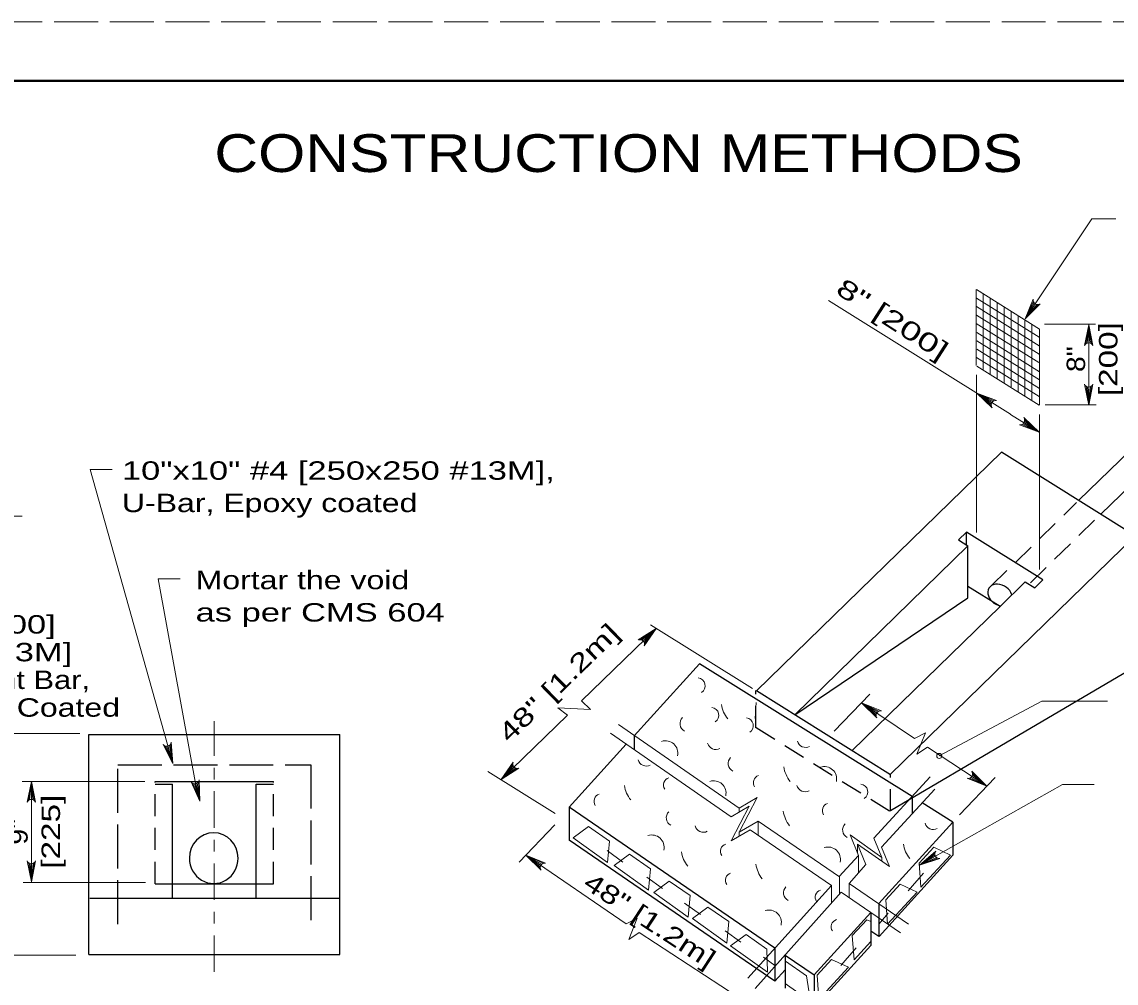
# Model space of a CAD drawing. Extents: x 1083.1 to 1117.1, y 697.4 to 741.4.
# Drawn here: x 1092.41 to 1101.68, y 733.21 to 741.35 of the extents above; entities that cross this region are included whole.
import ezdxf
from ezdxf.enums import TextEntityAlignment as Align

# ---------------------------------------------------------------- set-up
doc = ezdxf.new("R2010")
doc.units = 0
doc.header["$LTSCALE"] = 0.062
for name, pattern in [('DOT_DASHED', [7.7, 5, -1.2, 0.3, -1.2]), ('LONG_DASHED', [7.5, 6, -1.5]), ('MEDIUM_DASHED', [4.5, 3, -1.5])]:
    doc.linetypes.add(name, pattern=pattern)
doc.layers.add('1', color=7, linetype='Continuous', lineweight=13)

msp = doc.modelspace()

# ---------------------------------------------------------------- linework, layer by layer
at = {"layer": '1', "lineweight": 25}
for p, q in [((1085.12642, 740.85408), (1116.62642, 740.85408)), ((1101.35767, 737.30017), (1102.00192, 737.92825)), ((1101.54458, 737.18333), (1102.16675, 737.78975)), ((1098.62958, 735.68725), (1100.70367, 737.70908)), ((1101.83592, 737.00125), (1100.70367, 737.70908)), ((1099.764, 734.98167), (1101.83592, 737.00125)), ((1100.34017, 736.96608), (1100.40908, 737.03325)), ((1101.05608, 736.62858), (1100.40908, 737.03325)), ((1100.40908, 736.923), (1100.40908, 737.03325)), ((1098.95342, 735.48483), (1100.421, 736.91542)), ((1100.34017, 736.96608), (1100.421, 736.91542)), ((1100.421, 736.47508), (1100.421, 736.91542)), ((1100.69392, 736.4015), (1100.421, 736.57217)), ((1100.69208, 736.40342), (1100.90617, 736.61208)), ((1098.95342, 735.48483), (1100.421, 736.47508)), ((1099.4385, 735.1815), (1100.69233, 736.40367)), ((1097.593, 735.30817), (1098.148, 735.91767)), ((1099.94717, 734.79267), (1098.148, 735.91767)), ((1099.764, 734.67442), (1101.83592, 735.895)), ((1099.764, 734.97792), (1098.62958, 735.68725)), ((1092.977, 733.45633), (1092.977, 735.3185)), ((1092.977, 735.3185), (1095.101, 735.3185)), ((1095.101, 733.45633), (1095.101, 735.3185)), ((1097.04267, 734.70375), (1097.52775, 735.2365)), ((1097.593, 735.30817), (1097.593, 735.19125)), ((1093.53758, 734.92175), (1094.54058, 734.92175)), ((1093.53758, 734.897), (1093.685, 734.897)), ((1093.685, 733.92975), (1093.685, 734.897)), ((1094.393, 733.93225), (1094.393, 734.897)), ((1094.393, 734.897), (1094.54058, 734.897)), ((1099.94717, 734.79267), (1099.94717, 734.64633)), ((1097.04267, 734.70375), (1097.04267, 734.42308)), ((1098.78633, 733.51), (1097.04267, 734.70375)), ((1100.29392, 734.57583), (1100.03242, 734.73933)), ((1099.66692, 733.88725), (1100.29392, 734.57583)), ((1100.29392, 734.57583), (1100.29392, 734.29517)), ((1098.78633, 733.22933), (1097.04267, 734.42308)), ((1099.668, 733.60775), (1100.29392, 734.29517)), ((1093.683, 734.055), (1094.39467, 734.055)), ((1092.9855, 733.93208), (1095.09617, 733.93208)), ((1099.66692, 733.88725), (1099.66692, 733.60658)), ((1099.11717, 733.2835), (1099.59808, 733.81167)), ((1099.59808, 733.81167), (1099.59808, 733.531)), ((1099.66692, 733.60658), (1099.59808, 733.65375)), ((1098.78633, 733.51), (1098.78633, 733.22933)), ((1099.11717, 733.00283), (1099.59808, 733.531)), ((1092.977, 733.45633), (1095.101, 733.45633)), ((1098.87317, 733.45058), (1099.11717, 733.2835)), ((1098.87317, 733.45058), (1098.87317, 733.16992)), ((1098.78633, 733.22933), (1098.87317, 733.32467)), ((1099.11717, 733.2835), (1099.11717, 733.00283))]:
    msp.add_line(p, q, dxfattribs=at)
at = {"layer": '1'}
for p, q in [((1100.90592, 738.83825), (1101.46942, 739.68592)), ((1101.46942, 739.68592), (1101.67183, 739.68592)), ((1100.49067, 738.44467), (1100.49067, 739.08708)), ((1101.02683, 738.75192), (1100.49208, 739.08625)), ((1100.54967, 738.40483), (1100.54967, 739.05017)), ((1100.782, 738.03033), (1099.2385, 738.995)), ((1101.02233, 738.68317), (1100.49208, 739.01467)), ((1101.023, 738.61108), (1100.49267, 738.94258)), ((1100.60867, 738.36867), (1100.60867, 739.01333)), ((1100.66767, 738.335), (1100.66767, 738.97642)), ((1100.72667, 738.29892), (1100.72667, 738.93958)), ((1100.97533, 738.98442), (1100.90592, 738.83825)), ((1100.98167, 738.97375), (1100.90592, 738.83825)), ((1100.99017, 738.96617), (1100.90592, 738.83825)), ((1101.00375, 738.96058), (1100.90592, 738.83825)), ((1101.01583, 738.96), (1100.90592, 738.83825)), ((1101.02233, 738.539), (1100.49208, 738.8705)), ((1100.78567, 738.26275), (1100.78567, 738.90267)), ((1100.84467, 738.22283), (1100.84467, 738.86583)), ((1101.0205, 738.46833), (1100.49025, 738.79983)), ((1100.90367, 738.19042), (1100.90367, 738.82892)), ((1100.96267, 738.14783), (1100.96267, 738.79192)), ((1101.02583, 738.10783), (1101.02583, 738.7525)), ((1101.49942, 738.79292), (1101.06808, 738.79292)), ((1101.41892, 738.627), (1101.44375, 738.78908)), ((1101.42933, 738.63308), (1101.44375, 738.78908)), ((1101.44375, 738.63592), (1101.44375, 738.78908)), ((1101.45508, 738.63425), (1101.44375, 738.78908)), ((1101.46617, 738.62883), (1101.44375, 738.78908)), ((1101.02683, 738.32175), (1100.49642, 738.65308)), ((1101.02733, 738.39108), (1100.49708, 738.7225)), ((1101.02608, 738.24958), (1100.49592, 738.581)), ((1101.02425, 738.18008), (1100.494, 738.5115)), ((1101.02492, 738.10808), (1100.49458, 738.4395)), ((1100.49208, 737.02975), (1100.49208, 738.36342)), ((1100.62425, 738.12892), (1100.49442, 738.21008)), ((1100.619, 738.11525), (1100.49442, 738.21008)), ((1100.61875, 738.10317), (1100.49442, 738.21008)), ((1100.63167, 738.13767), (1100.49442, 738.21008)), ((1100.64217, 738.14417), (1100.49442, 738.21008)), ((1101.42133, 738.26808), (1101.44375, 738.10783)), ((1101.43242, 738.26267), (1101.44375, 738.10783)), ((1101.4685, 738.27), (1101.44375, 738.10783)), ((1101.45808, 738.26383), (1101.44375, 738.10783)), ((1101.44375, 738.261), (1101.44375, 738.10783)), ((1101.50517, 738.10983), (1101.07392, 738.10983)), ((1101.02467, 737.87867), (1100.78133, 738.02942)), ((1101.02725, 736.717), (1101.02725, 738.02783)), ((1100.87683, 737.94458), (1101.02467, 737.87867)), ((1100.88733, 737.95108), (1101.02467, 737.87867)), ((1100.89475, 737.95983), (1101.02467, 737.87867)), ((1100.9, 737.9735), (1101.02467, 737.87867)), ((1100.90025, 737.98558), (1101.02467, 737.87867)), ((1092.4125, 737.16733), (1090.73225, 737.16733)), ((1098.59508, 735.70875), (1097.73383, 736.24742)), ((1097.6475, 736.12167), (1097.781, 736.21692)), ((1097.65917, 736.1185), (1097.781, 736.21692)), ((1097.67117, 736.11017), (1097.781, 736.21692)), ((1097.67792, 736.10083), (1097.781, 736.21692)), ((1097.68175, 736.08908), (1097.781, 736.21692)), ((1099.59025, 735.66092), (1099.28742, 735.34542)), ((1099.64875, 735.50258), (1099.52058, 735.58642)), ((1099.64325, 735.489), (1099.52058, 735.58642)), ((1099.64275, 735.47692), (1099.52058, 735.58642)), ((1099.65633, 735.51117), (1099.52058, 735.58642)), ((1099.667, 735.51742), (1099.52058, 735.58642)), ((1099.96708, 735.28325), (1099.52058, 735.58642)), ((1093.65942, 735.22658), (1093.68692, 735.07233)), ((1093.66783, 735.23525), (1093.68692, 735.07233)), ((1093.62283, 735.22092), (1093.68692, 735.07233)), ((1093.63492, 735.21858), (1093.68692, 735.07233)), ((1093.64625, 735.22), (1093.68692, 735.07233)), ((1100.58125, 734.8805), (1100.07775, 735.21092)), ((1096.56625, 735.06375), (1096.467, 734.936)), ((1096.57008, 735.052), (1096.467, 734.936)), ((1096.57683, 735.04275), (1096.467, 734.936)), ((1096.92392, 734.65042), (1096.35617, 735.00542)), ((1096.58883, 735.03442), (1096.467, 734.936)), ((1096.6005, 735.03125), (1096.467, 734.936)), ((1100.65092, 734.955), (1100.34792, 734.6395)), ((1100.43483, 734.94942), (1100.58125, 734.8805)), ((1100.44542, 734.95567), (1100.58125, 734.8805)), ((1100.453, 734.96425), (1100.58125, 734.8805)), ((1100.45858, 734.97792), (1100.58125, 734.8805)), ((1100.45908, 734.98992), (1100.58125, 734.8805)), ((1093.45, 734.92175), (1092.41233, 734.92175)), ((1092.46508, 734.75958), (1092.48983, 734.92175)), ((1092.47542, 734.76575), (1092.48983, 734.92175)), ((1092.48983, 734.071), (1092.48983, 734.92175)), ((1092.48983, 734.76858), (1092.48983, 734.92175)), ((1092.50117, 734.76692), (1092.48983, 734.92175)), ((1092.51225, 734.7615), (1092.48983, 734.92175)), ((1093.85817, 734.90408), (1093.91617, 734.753)), ((1093.87017, 734.90125), (1093.91617, 734.753)), ((1093.8815, 734.90217), (1093.91617, 734.753)), ((1093.89492, 734.90825), (1093.91617, 734.753)), ((1093.90375, 734.91658), (1093.91617, 734.753)), ((1100.0115, 734.21167), (1101.22067, 734.89417)), ((1101.22067, 734.89417), (1101.49075, 734.89417)), ((1098.48333, 734.69517), (1098.48333, 734.66167)), ((1098.64558, 734.58517), (1098.64558, 734.46517)), ((1099.33208, 734.11417), (1098.64558, 734.58517)), ((1096.92383, 734.55408), (1096.621, 734.23858)), ((1098.48333, 734.49092), (1098.48333, 734.45708)), ((1099.26433, 734.04067), (1098.57758, 734.51183)), ((1099.42208, 734.46833), (1099.49342, 734.29483)), ((1099.4855, 734.39108), (1099.4855, 734.31283)), ((1097.36533, 734.33467), (1097.4995, 734.23767)), ((1100.13975, 734.31025), (1100.0115, 734.21167)), ((1100.1405, 734.29792), (1100.0115, 734.21167)), ((1092.46742, 734.23125), (1092.48983, 734.071)), ((1092.4785, 734.22583), (1092.48983, 734.071)), ((1092.51458, 734.23317), (1092.48983, 734.071)), ((1092.50425, 734.227), (1092.48983, 734.071)), ((1092.48983, 734.22417), (1092.48983, 734.071)), ((1096.80475, 734.21267), (1096.67658, 734.2965)), ((1096.79925, 734.19908), (1096.67658, 734.2965)), ((1096.79875, 734.187), (1096.67658, 734.2965)), ((1096.81233, 734.22125), (1096.67658, 734.2965)), ((1096.823, 734.2275), (1096.67658, 734.2965)), ((1097.52708, 733.71425), (1096.67658, 734.2965)), ((1099.33117, 734.11475), (1099.49342, 734.29483)), ((1099.49342, 734.29483), (1099.49342, 734.14642)), ((1099.69192, 734.27808), (1099.69192, 734.2455)), ((1100.14467, 734.28725), (1100.0115, 734.21167)), ((1100.15425, 734.27617), (1100.0115, 734.21167)), ((1100.16475, 734.27017), (1100.0115, 734.21167)), ((1099.33308, 734.11433), (1099.33308, 733.96658)), ((1099.91475, 733.99533), (1100.04525, 734.1445)), ((1093.45692, 734.06608), (1092.41942, 734.06608)), ((1097.70083, 734.111), (1097.835, 734.014)), ((1098.55658, 733.25492), (1099.26433, 734.04067)), ((1099.26417, 734.04042), (1099.26417, 733.89267)), ((1099.41433, 734.05775), (1099.41433, 733.93775)), ((1098.61942, 733.16592), (1099.34742, 733.98267)), ((1099.84967, 733.63908), (1099.34758, 733.98358)), ((1098.02133, 733.891), (1098.1555, 733.794)), ((1099.66692, 733.7135), (1099.74617, 733.80408)), ((1098.36425, 733.65608), (1098.49842, 733.55908)), ((1098.71317, 732.93875), (1097.63775, 733.64192)), ((1099.3445, 733.3615), (1099.475, 733.51067)), ((1092.86575, 733.45017), (1090.709, 733.45017)), ((1098.68858, 733.43242), (1098.78633, 733.36175))]:
    msp.add_line(p, q, dxfattribs=at)
at = {"layer": '1', "linetype": 'MEDIUM_DASHED', "lineweight": 25}
for p, q in [((1100.61717, 736.57675), (1101.34083, 737.28225)), ((1100.94992, 736.60367), (1101.54458, 737.18342)), ((1098.62475, 735.37525), (1098.62475, 735.69017)), ((1099.75583, 734.66867), (1098.62517, 735.37542)), ((1099.764, 734.66967), (1099.764, 734.98167)), ((1093.53758, 734.055), (1093.53758, 734.92175)), ((1094.54058, 734.055), (1094.54058, 734.92175)), ((1093.53758, 734.055), (1093.68542, 734.055)), ((1094.38983, 734.055), (1094.54058, 734.055))]:
    msp.add_line(p, q, dxfattribs=at)
at = {"layer": '1', "linetype": 'MEDIUM_DASHED'}
msp.add_line((1098.62017, 735.4545), (1098.62783, 735.58917), dxfattribs=at)
at = {"layer": '1', "linetype": 'DOT_DASHED'}
msp.add_line((1094.039, 733.30725), (1094.039, 735.431), dxfattribs=at)
at = {"layer": '1', "linetype": 'LONG_DASHED'}
msp.add_lwpolyline([(1083.12642, 719.35408), (1117.12642, 719.35408), (1117.12642, 741.35408), (1083.12642, 741.35408)], close=True, dxfattribs=at)
at = {"layer": '1', "lineweight": 40}
msp.add_lwpolyline([(1085.12642, 740.85408), (1116.62642, 740.85408), (1116.62642, 719.85408), (1085.12642, 719.85408)], close=True, dxfattribs=at)
msp.add_lwpolyline([(1085.12642, 740.85408), (1116.62642, 740.85408), (1116.62642, 719.85408), (1085.12642, 719.85408)], close=True, dxfattribs=at)
at = {"layer": '1'}
for points in [[(1101.03283, 738.96658), (1100.90592, 738.83825), (1100.97375, 739.0055)], [(1101.40833, 738.61208), (1101.44375, 738.78908), (1101.47908, 738.61208)], [(1101.44375, 738.10783), (1101.44375, 738.56575), (1101.44375, 738.78908)], [(1101.47908, 738.28483), (1101.44375, 738.10783), (1101.40833, 738.28483)], [(1100.62567, 738.08625), (1100.49442, 738.21008), (1100.66325, 738.14633)], [(1100.89333, 738.0025), (1101.02467, 737.87867), (1100.85575, 737.94242)], [(1093.17508, 737.56367), (1092.98908, 737.56367), (1093.68783, 735.072)], [(1093.75075, 736.6365), (1093.56475, 736.6365), (1093.89392, 734.82675)], [(1096.467, 734.936), (1097.02967, 735.48292), (1096.94833, 735.5455), (1097.22517, 735.53092), (1097.14958, 735.60292), (1097.781, 736.21692)], [(1097.62942, 736.11892), (1097.781, 736.21692), (1097.67875, 736.06817)], [(1100.17725, 735.13675), (1101.04675, 735.60017), (1101.60267, 735.60017)], [(1099.64933, 735.45992), (1099.52058, 735.58642), (1099.68808, 735.51917)], [(1087.54775, 735.32775), (1090.51608, 735.32775), (1092.9005, 735.32775)], [(1097.39433, 735.32883), (1098.41533, 734.62183), (1098.56717, 734.71083), (1098.41533, 734.41758), (1098.57758, 734.51183)], [(1097.46233, 735.40217), (1098.48333, 734.69517), (1098.63517, 734.78417), (1098.48333, 734.49092), (1098.64558, 734.58517)], [(1099.96708, 735.28325), (1100.06075, 735.33275), (1099.98883, 735.15158), (1100.07775, 735.21092)], [(1093.67408, 735.25242), (1093.68692, 735.07233), (1093.60583, 735.23358)], [(1096.61858, 735.034), (1096.467, 734.936), (1096.56925, 735.08475)], [(1100.10108, 734.96058), (1099.62442, 734.44067), (1099.69192, 734.27808), (1099.42208, 734.46833)], [(1100.4525, 735.007), (1100.58125, 734.8805), (1100.41375, 734.94767)], [(1092.45442, 734.74475), (1092.48983, 734.92175), (1092.52525, 734.74475)], [(1093.91067, 734.93342), (1093.91617, 734.753), (1093.84167, 734.91742)], [(1100.139, 734.85558), (1099.68775, 734.36333), (1099.75533, 734.20075), (1099.4855, 734.39108), (1099.55675, 734.2175)], [(1100.18292, 734.26825), (1100.0115, 734.21167), (1100.14792, 734.32983)], [(1092.52525, 734.248), (1092.48983, 734.071), (1092.45442, 734.248)], [(1096.80533, 734.17), (1096.67658, 734.2965), (1096.84408, 734.22925)], [(1099.91767, 733.71242), (1099.41433, 734.05775), (1099.55675, 734.2175)], [(1097.52708, 733.71425), (1097.62075, 733.76375), (1097.54883, 733.58258), (1097.63775, 733.64192)], [(1099.59808, 733.56442), (1099.45642, 733.41), (1099.4415, 733.61508), (1099.5645, 733.74933), (1099.59808, 733.73342)], [(1098.87317, 733.3975), (1098.87492, 733.39883), (1099.05217, 733.275), (1099.08667, 733.05583), (1098.87317, 733.2095)]]:
    msp.add_lwpolyline(points, dxfattribs=at)
at = {"layer": '1', "lineweight": 25}
msp.add_lwpolyline([(1100.90617, 736.61208), (1100.98717, 736.56142), (1101.05608, 736.62858)], dxfattribs=at)
at = {"layer": '1', "linetype": 'LONG_DASHED', "lineweight": 25}
msp.add_lwpolyline([(1093.2225, 733.712), (1093.2225, 735.06283), (1094.85558, 735.06283), (1094.85558, 733.712)], dxfattribs=at)
at = {"layer": '1'}
for points in [[(1097.07842, 734.44283), (1097.20883, 734.53975), (1097.38608, 734.41592), (1097.36908, 734.234)], [(1097.42508, 734.20792), (1097.5555, 734.30483), (1097.73275, 734.181), (1097.71575, 733.99908)], [(1100.02292, 734.02508), (1100.008, 734.23017), (1100.131, 734.36442), (1100.27258, 734.29725)], [(1097.7605, 733.9805), (1097.89092, 734.07742), (1098.06817, 733.95358), (1098.05117, 733.77167)], [(1099.73967, 733.712), (1099.72475, 733.91708), (1099.84775, 734.05133), (1099.98933, 733.98417)], [(1098.0885, 733.7605), (1098.21892, 733.85742), (1098.39617, 733.73358), (1098.37917, 733.55167)], [(1098.41125, 733.52783), (1098.54167, 733.62475), (1098.71892, 733.50092), (1098.72292, 733.30492)], [(1099.15817, 733.07442), (1099.14325, 733.2795), (1099.26625, 733.41375), (1099.40783, 733.34658)]]:
    msp.add_lwpolyline(points, close=True, dxfattribs=at)
msp.add_circle((1100.17725, 735.13675), 0.02142, dxfattribs=at)
for centre, radius, start, end in [((1101.01111, 738.99801), 0.0382, 168.72921, 304.55533), ((1101.44375, 738.59781), 0.0382, 22.08782, 157.91395), ((1101.44368, 738.29914), 0.0382, 202.08782, 337.91395), ((1100.65661, 738.10874), 0.0382, 80.07633, 215.90246), ((1100.8624, 737.98), 0.0382, 260.07633, 35.90246), ((1097.64389, 736.08352), 0.0382, 336.28517, 112.1113), ((1098.12842, 735.73125), 0.06689, 303.67027, 82.84336), ((1098.24442, 735.48075), 0.06689, 303.67027, 82.84336), ((1098.59683, 735.61533), 0.26761, 188.97541, 218.01059), ((1099.68071, 735.48175), 0.0382, 78.90799, 214.73412), ((1098.05425, 735.41125), 0.07212, 135, 242.45942), ((1098.5365, 735.39267), 0.06689, 303.67027, 82.84336), ((1093.63613, 735.25678), 0.0382, 217.46338, 353.28951), ((1097.8595, 735.16075), 0.10462, 347.15932, 108.38347), ((1098.28608, 735.26275), 0.072, 194.8887, 297.82099), ((1099.04667, 735.28125), 0.072, 194.8887, 297.82099), ((1096.60411, 735.06937), 0.0382, 156.27266, 292.09878), ((1097.69717, 735.12358), 0.072, 194.8887, 297.82099), ((1098.46233, 735.07267), 0.07212, 135, 242.45942), ((1099.1255, 735.0865), 0.26761, 188.97541, 218.01059), ((1099.20433, 734.94275), 0.10462, 347.15932, 108.38347), ((1097.90583, 734.89167), 0.06313, 107.11941, 214.34733), ((1098.66642, 734.91017), 0.06313, 107.11941, 214.34733), ((1100.42115, 734.98511), 0.0382, 258.90799, 34.73412), ((1093.87295, 734.93932), 0.0382, 215.13546, 350.96158), ((1097.776, 734.92883), 0.26761, 188.97541, 218.01059), ((1098.26758, 734.82217), 0.10462, 347.15932, 108.38347), ((1099.042, 734.90558), 0.072, 194.8887, 297.82099), ((1099.50575, 734.83133), 0.06689, 303.67027, 82.84336), ((1092.48988, 734.73042), 0.0382, 22.08782, 157.91395), ((1097.31692, 734.7525), 0.06313, 107.11941, 214.34733), ((1099.12083, 734.71083), 0.26761, 188.97541, 218.01059), ((1099.25067, 734.67367), 0.06313, 107.11941, 214.34733), ((1097.93833, 734.61342), 0.07212, 135, 242.45942), ((1098.17942, 734.56233), 0.072, 194.8887, 297.82099), ((1099.43158, 734.51133), 0.07212, 135, 242.45942), ((1100.12717, 734.5855), 0.072, 194.8887, 297.82099), ((1097.74358, 734.36292), 0.10462, 347.15932, 108.38347), ((1098.38808, 734.33042), 0.06313, 107.11941, 214.34733), ((1100.13792, 734.43267), 0.26761, 188.97541, 218.01059), ((1098.25825, 734.36758), 0.26761, 188.97541, 218.01059), ((1099.23683, 734.26083), 0.10462, 347.15932, 108.38347), ((1100.17782, 734.30612), 0.0382, 141.67569, 277.50181), ((1092.4898, 734.26232), 0.0382, 202.08782, 337.91395), ((1096.83669, 734.1918), 0.0382, 78.90799, 214.73412), ((1098.889, 734.26083), 0.26761, 188.97541, 218.01059), ((1098.42992, 734.0845), 0.06313, 107.11941, 214.34733), ((1098.93075, 733.97792), 0.07212, 135, 242.45942), ((1099.19042, 733.94075), 0.06313, 107.11941, 214.34733), ((1098.736, 733.72742), 0.10462, 347.15932, 108.38347), ((1099.32483, 733.69025), 0.06313, 107.11941, 214.34733)]:
    msp.add_arc(centre, radius, start, end, dxfattribs=at)
at = {"layer": '1', "lineweight": 25}
for centre, major_axis, ratio, start_param, end_param in [((1100.69209, 736.49924), (-0.09318, 0.05987), 0.765567, 3.8765612, 8.3520117), ((1094.03424, 734.27142), (0, 0.2151), 0.96, 4.712389, 7.8539816), ((1094.03424, 734.27142), (0, 0.2151), 0.96, 1.5707963, 4.712389)]:
    msp.add_ellipse(centre, major_axis=major_axis, ratio=ratio, start_param=start_param, end_param=end_param, dxfattribs=at)

# ---------------------------------------------------------------- texts
at = {"layer": '1'}
for s, height, width, p in [('CONSTRUCTION METHODS', 0.32, 1.2, (1094.039, 740.08242)), ('10"x10" #4 [250x250 #13M],', 0.156, 1.4, (1093.25633, 737.47608)), ('U-Bar, Epoxy coated', 0.156, 1.3, (1093.25633, 737.20208)), ('Mortar the void ', 0.156, 1.3, (1093.88075, 736.54892)), ('as per CMS 604', 0.156, 1.4, (1093.88075, 736.27492)), ('28" [700]', 0.156, 1.4, (1091.53708, 736.17317)), ('#4 [#13M]', 0.156, 1.4, (1091.53708, 735.9385)), ('Straight Bar,', 0.156, 1.25, (1091.53708, 735.70383)), ('Epoxy Coated', 0.156, 1.3, (1091.53708, 735.46917))]:
    msp.add_text(s, height=height, dxfattribs=dict(at, width=width)).set_placement(p)
for s, rotation, width, p in [('8" [200]', 327.247, 1.5, (1099.28992, 739.06042)), ('48" [1.2m]', 44.268, 1.4, (1096.53642, 735.23992)), ('48" [1.2m]', 326.819, 1.35, (1097.15083, 734.02875))]:
    msp.add_text(s, height=0.156, rotation=rotation, dxfattribs=dict(at, width=width)).set_placement(p)
for s, width, p in [('[200]', 1.35, (1101.68617, 738.49758)), ('8"', 1.15, (1101.41217, 738.49758)), ('[225]', 1.35, (1092.73233, 734.495)), ('9"', 1.15, (1092.45833, 734.495))]:
    msp.add_text(s, height=0.156, rotation=90, dxfattribs=dict(at, width=width)).set_placement(p, align=Align.CENTER)

doc.saveas('drawing.dxf')
